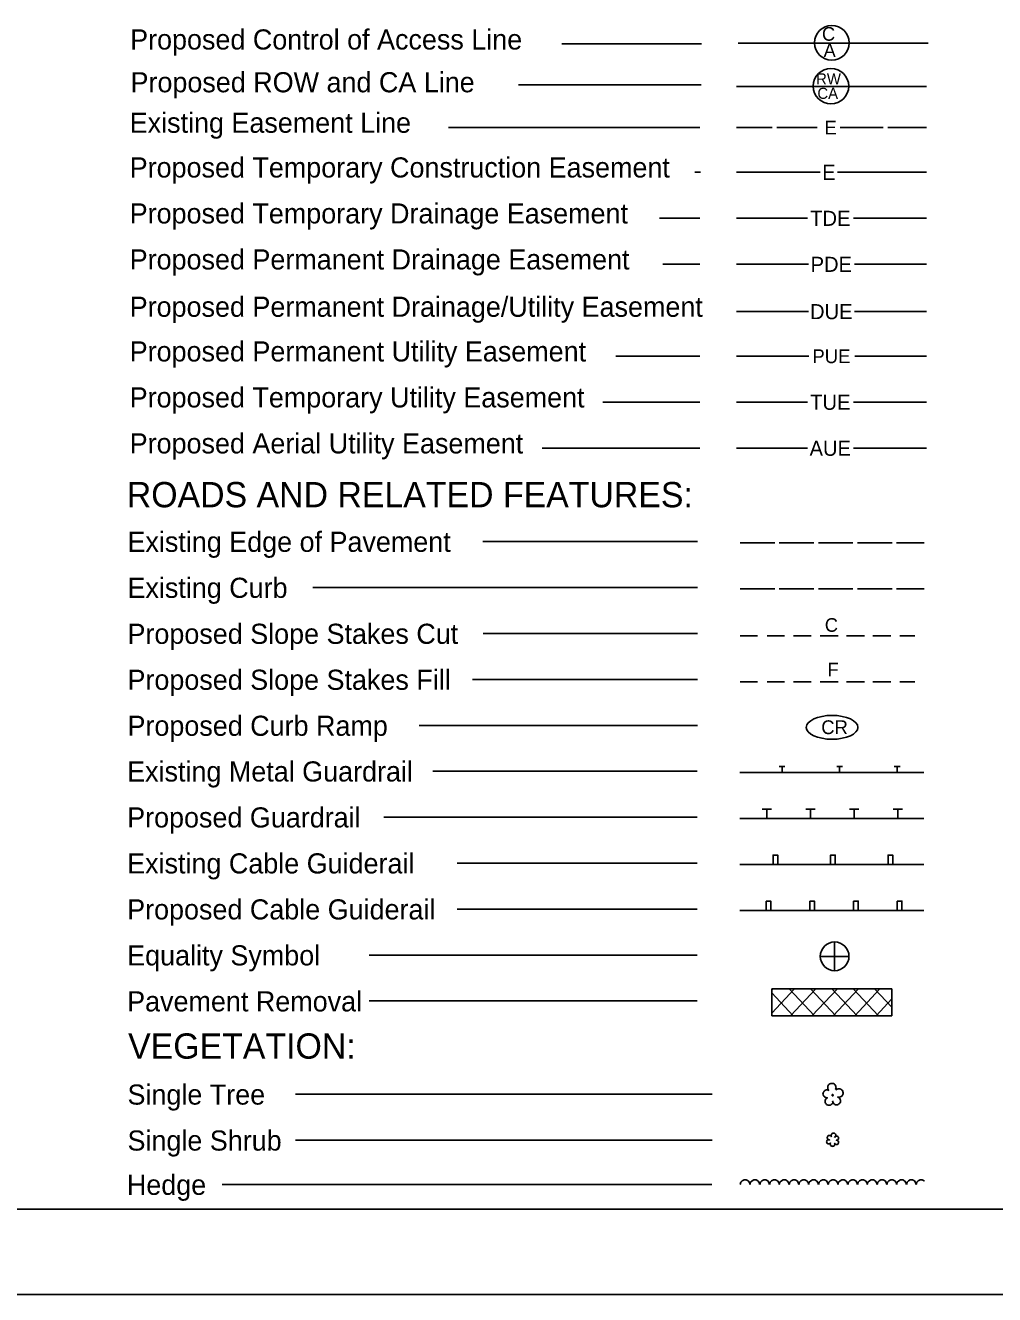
# Model space of a CAD drawing. Extents: x 1552903 to 1553044, y 811448 to 811540.
# Drawn here: x 1552937.98 to 1552973.4, y 811448.42 to 811494.83 of the extents above; entities that cross this region are included whole.
import ezdxf

# ---------------------------------------------------------------- set-up
doc = ezdxf.new("R2010")
doc.units = 0
for name, color, linetype in [('Exist DTM Breakline', 7, 'Continuous'), ('Exist Structure Major Bridge WW', 7, 'Continuous'), ('P_RDY_Easement_Permanent_Drainage_Utility', 7, 'Continuous'), ('P_RDY_WCC_CELL', 7, 'Continuous'), ('z - Construction', 7, 'Continuous')]:
    doc.layers.add(name, color=color, linetype=linetype)

msp = doc.modelspace()

# ---------------------------------------------------------------- linework, layer by layer
at = {"layer": 'Exist DTM Breakline'}
for p, q in [((1552962.683, 811494.155), (1552957.579, 811494.155)), ((1552964.031, 811494.186), (1552970.967, 811494.186)), ((1552962.675, 811492.662), (1552956.002, 811492.662)), ((1552963.97, 811492.597), (1552970.906, 811492.597)), ((1552962.621, 811491.096), (1552953.436, 811491.096)), ((1552963.969, 811491.096), (1552965.273, 811491.096)), ((1552965.441, 811491.096), (1552966.913, 811491.096)), ((1552967.754, 811491.096), (1552969.33, 811491.096)), ((1552969.498, 811491.096), (1552970.905, 811491.096)), ((1552962.654, 811489.461), (1552962.442, 811489.461)), ((1552963.969, 811489.461), (1552964.189, 811489.461)), ((1552964.189, 811489.461), (1552967.026, 811489.461)), ((1552967.657, 811489.461), (1552970.495, 811489.461)), ((1552970.495, 811489.461), (1552970.905, 811489.461)), ((1552962.621, 811487.779), (1552961.15, 811487.779)), ((1552963.969, 811487.779), (1552964.251, 811487.779)), ((1552964.251, 811487.779), (1552966.563, 811487.779)), ((1552968.244, 811487.779), (1552970.557, 811487.779)), ((1552970.557, 811487.779), (1552970.905, 811487.779)), ((1552962.621, 811486.098), (1552961.275, 811486.098)), ((1552963.969, 811486.098), (1552964.289, 811486.098)), ((1552964.289, 811486.098), (1552966.601, 811486.098)), ((1552968.282, 811486.098), (1552970.594, 811486.098)), ((1552970.594, 811486.098), (1552970.905, 811486.098)), ((1552962.621, 811482.734), (1552959.56, 811482.734)), ((1552963.969, 811482.734), (1552964.292, 811482.734)), ((1552964.292, 811482.734), (1552966.604, 811482.734)), ((1552968.285, 811482.734), (1552970.598, 811482.734)), ((1552970.598, 811482.734), (1552970.905, 811482.734)), ((1552962.621, 811481.052), (1552959.078, 811481.052)), ((1552963.969, 811481.052), (1552964.251, 811481.052)), ((1552964.251, 811481.052), (1552966.563, 811481.052)), ((1552968.244, 811481.052), (1552970.557, 811481.052)), ((1552970.557, 811481.052), (1552970.905, 811481.052)), ((1552962.621, 811479.371), (1552956.866, 811479.371)), ((1552963.969, 811479.371), (1552964.251, 811479.371)), ((1552964.251, 811479.371), (1552966.563, 811479.371)), ((1552968.244, 811479.371), (1552970.557, 811479.371)), ((1552970.557, 811479.371), (1552970.905, 811479.371)), ((1552962.54, 811475.963), (1552954.701, 811475.963)), ((1552964.098, 811475.915), (1552965.36, 811475.915)), ((1552965.528, 811475.915), (1552966.789, 811475.915)), ((1552966.957, 811475.915), (1552968.218, 811475.915)), ((1552968.386, 811475.915), (1552969.648, 811475.915)), ((1552969.816, 811475.915), (1552970.825, 811475.915)), ((1552962.54, 811474.282), (1552948.487, 811474.282)), ((1552964.098, 811474.233), (1552965.36, 811474.233)), ((1552965.528, 811474.233), (1552966.789, 811474.233)), ((1552966.957, 811474.233), (1552968.218, 811474.233)), ((1552968.386, 811474.233), (1552969.648, 811474.233)), ((1552969.816, 811474.233), (1552970.825, 811474.233)), ((1552962.54, 811472.6), (1552954.705, 811472.6)), ((1552964.098, 811472.512), (1552964.737, 811472.512)), ((1552965.721, 811472.512), (1552965.086, 811472.512)), ((1552966.688, 811472.512), (1552966.049, 811472.512)), ((1552967.676, 811472.512), (1552967.02, 811472.512)), ((1552968.639, 811472.512), (1552967.987, 811472.512)), ((1552969.61, 811472.512), (1552968.95, 811472.512)), ((1552970.476, 811472.512), (1552969.938, 811472.512)), ((1552962.54, 811470.918), (1552954.323, 811470.918)), ((1552964.098, 811470.83), (1552964.737, 811470.83)), ((1552965.721, 811470.83), (1552965.086, 811470.83)), ((1552966.688, 811470.83), (1552966.049, 811470.83)), ((1552967.676, 811470.83), (1552967.02, 811470.83)), ((1552968.639, 811470.83), (1552967.987, 811470.83)), ((1552969.61, 811470.83), (1552968.95, 811470.83)), ((1552970.476, 811470.83), (1552969.938, 811470.83)), ((1552962.54, 811469.237), (1552952.373, 811469.237)), ((1552962.527, 811467.565), (1552952.872, 811467.565)), ((1552964.085, 811467.517), (1552970.811, 811467.517)), ((1552965.526, 811467.727), (1552965.736, 811467.727)), ((1552965.631, 811467.517), (1552965.631, 811467.727)), ((1552967.628, 811467.727), (1552967.838, 811467.727)), ((1552967.733, 811467.517), (1552967.733, 811467.727)), ((1552969.73, 811467.727), (1552969.94, 811467.727)), ((1552969.835, 811467.517), (1552969.835, 811467.727)), ((1552964.903, 811466.168), (1552965.239, 811466.168)), ((1552965.071, 811465.835), (1552965.071, 811466.168)), ((1552966.5, 811466.168), (1552966.837, 811466.168)), ((1552966.669, 811465.835), (1552966.669, 811466.168)), ((1552968.098, 811466.168), (1552968.434, 811466.168)), ((1552968.266, 811465.835), (1552968.266, 811466.168)), ((1552969.695, 811466.168), (1552970.032, 811466.168)), ((1552969.863, 811465.835), (1552969.863, 811466.168)), ((1552962.527, 811465.884), (1552951.073, 811465.884)), ((1552970.811, 811465.835), (1552964.085, 811465.835)), ((1552962.527, 811464.202), (1552953.758, 811464.202)), ((1552964.085, 811464.154), (1552970.811, 811464.154)), ((1552962.527, 811462.521), (1552953.758, 811462.521)), ((1552964.085, 811462.472), (1552970.811, 811462.472)), ((1552967.551, 811461.315), (1552967.551, 811460.79)), ((1552962.527, 811460.839), (1552950.536, 811460.839)), ((1552967.026, 811460.79), (1552967.551, 811460.79)), ((1552967.551, 811460.79), (1552967.551, 811460.264)), ((1552967.551, 811460.79), (1552968.077, 811460.79)), ((1552965.258, 811459.602), (1552969.639, 811459.602)), ((1552965.258, 811458.618), (1552965.258, 811459.602)), ((1552965.258, 811459.552), (1552965.304, 811459.602)), ((1552965.258, 811458.715), (1552966.086, 811459.602)), ((1552966.818, 811458.618), (1552965.893, 811459.602)), ((1552965.943, 811458.618), (1552966.868, 811459.602)), ((1552967.595, 811458.618), (1552966.675, 811459.602)), ((1552966.721, 811458.618), (1552967.65, 811459.602)), ((1552968.377, 811458.618), (1552967.453, 811459.602)), ((1552967.503, 811458.618), (1552968.428, 811459.602)), ((1552969.159, 811458.618), (1552968.23, 811459.602)), ((1552968.285, 811458.618), (1552969.206, 811459.602)), ((1552969.639, 811458.934), (1552969.012, 811459.602)), ((1552969.639, 811459.602), (1552969.639, 811458.618)), ((1552962.527, 811459.158), (1552950.536, 811459.158)), ((1552966.036, 811458.618), (1552965.258, 811459.451)), ((1552969.063, 811458.618), (1552969.639, 811459.232)), ((1552969.639, 811458.618), (1552965.258, 811458.618)), ((1552963.081, 811455.749), (1552947.852, 811455.749)), ((1552963.081, 811454.067), (1552947.852, 811454.067)), ((1552963.058, 811452.448), (1552945.176, 811452.448)), ((1552964.1, 811452.448), (1552964.125, 811452.528)), ((1552964.125, 811452.528), (1552964.176, 811452.582)), ((1552964.176, 811452.582), (1552964.243, 811452.62)), ((1552964.243, 811452.62), (1552964.323, 811452.62)), ((1552964.323, 811452.62), (1552964.39, 811452.578)), ((1552964.39, 811452.578), (1552964.436, 811452.524)), ((1552964.436, 811452.524), (1552964.453, 811452.452)), ((1552964.457, 811452.448), (1552964.482, 811452.528)), ((1552964.482, 811452.528), (1552964.533, 811452.582)), ((1552964.533, 811452.582), (1552964.6, 811452.62)), ((1552964.6, 811452.62), (1552964.68, 811452.62)), ((1552964.68, 811452.62), (1552964.747, 811452.578)), ((1552964.747, 811452.578), (1552964.794, 811452.524)), ((1552964.794, 811452.524), (1552964.81, 811452.452)), ((1552964.815, 811452.448), (1552964.84, 811452.528)), ((1552964.84, 811452.528), (1552964.89, 811452.582)), ((1552964.89, 811452.582), (1552964.958, 811452.62)), ((1552964.958, 811452.62), (1552965.037, 811452.62)), ((1552965.037, 811452.62), (1552965.105, 811452.578)), ((1552965.105, 811452.578), (1552965.151, 811452.524)), ((1552965.151, 811452.524), (1552965.168, 811452.452)), ((1552965.172, 811452.448), (1552965.197, 811452.528)), ((1552965.197, 811452.528), (1552965.248, 811452.582)), ((1552965.248, 811452.582), (1552965.315, 811452.62)), ((1552965.315, 811452.62), (1552965.395, 811452.62)), ((1552965.395, 811452.62), (1552965.462, 811452.578)), ((1552965.462, 811452.578), (1552965.508, 811452.524)), ((1552965.508, 811452.524), (1552965.525, 811452.452)), ((1552965.529, 811452.448), (1552965.554, 811452.528)), ((1552965.554, 811452.528), (1552965.605, 811452.582)), ((1552965.605, 811452.582), (1552965.672, 811452.62)), ((1552965.672, 811452.62), (1552965.752, 811452.62)), ((1552965.752, 811452.62), (1552965.819, 811452.578)), ((1552965.819, 811452.578), (1552965.866, 811452.524)), ((1552965.866, 811452.524), (1552965.882, 811452.452)), ((1552965.887, 811452.448), (1552965.912, 811452.528)), ((1552965.912, 811452.528), (1552965.962, 811452.582)), ((1552965.962, 811452.582), (1552966.03, 811452.62)), ((1552966.03, 811452.62), (1552966.109, 811452.62)), ((1552966.109, 811452.62), (1552966.177, 811452.578)), ((1552966.177, 811452.578), (1552966.223, 811452.524)), ((1552966.223, 811452.524), (1552966.24, 811452.452)), ((1552966.244, 811452.448), (1552966.269, 811452.528)), ((1552966.269, 811452.528), (1552966.32, 811452.582)), ((1552966.32, 811452.582), (1552966.387, 811452.62)), ((1552966.387, 811452.62), (1552966.467, 811452.62)), ((1552966.467, 811452.62), (1552966.534, 811452.578)), ((1552966.534, 811452.578), (1552966.58, 811452.524)), ((1552966.58, 811452.524), (1552966.597, 811452.452)), ((1552966.601, 811452.448), (1552966.626, 811452.528)), ((1552966.626, 811452.528), (1552966.677, 811452.582)), ((1552966.677, 811452.582), (1552966.744, 811452.62)), ((1552966.744, 811452.62), (1552966.824, 811452.62)), ((1552966.824, 811452.62), (1552966.891, 811452.578)), ((1552966.891, 811452.578), (1552966.938, 811452.524)), ((1552966.938, 811452.524), (1552966.954, 811452.452)), ((1552966.959, 811452.448), (1552966.984, 811452.528)), ((1552966.984, 811452.528), (1552967.034, 811452.582)), ((1552967.034, 811452.582), (1552967.102, 811452.62)), ((1552967.102, 811452.62), (1552967.181, 811452.62)), ((1552967.181, 811452.62), (1552967.249, 811452.578)), ((1552967.249, 811452.578), (1552967.295, 811452.524)), ((1552967.295, 811452.524), (1552967.312, 811452.452)), ((1552967.316, 811452.448), (1552967.341, 811452.528)), ((1552967.341, 811452.528), (1552967.392, 811452.582)), ((1552967.392, 811452.582), (1552967.459, 811452.62)), ((1552967.459, 811452.62), (1552967.539, 811452.62)), ((1552967.539, 811452.62), (1552967.606, 811452.578)), ((1552967.606, 811452.578), (1552967.652, 811452.524)), ((1552967.652, 811452.524), (1552967.669, 811452.452)), ((1552967.673, 811452.448), (1552967.698, 811452.528)), ((1552967.698, 811452.528), (1552967.749, 811452.582)), ((1552967.749, 811452.582), (1552967.816, 811452.62)), ((1552967.816, 811452.62), (1552967.896, 811452.62)), ((1552967.896, 811452.62), (1552967.963, 811452.578)), ((1552967.963, 811452.578), (1552968.01, 811452.524)), ((1552968.01, 811452.524), (1552968.026, 811452.452)), ((1552968.031, 811452.448), (1552968.056, 811452.528)), ((1552968.056, 811452.528), (1552968.106, 811452.582)), ((1552968.106, 811452.582), (1552968.174, 811452.62)), ((1552968.174, 811452.62), (1552968.253, 811452.62)), ((1552968.253, 811452.62), (1552968.321, 811452.578)), ((1552968.321, 811452.578), (1552968.367, 811452.524)), ((1552968.367, 811452.524), (1552968.384, 811452.452)), ((1552968.388, 811452.448), (1552968.413, 811452.528)), ((1552968.413, 811452.528), (1552968.464, 811452.582)), ((1552968.464, 811452.582), (1552968.531, 811452.62)), ((1552968.531, 811452.62), (1552968.611, 811452.62)), ((1552968.611, 811452.62), (1552968.678, 811452.578)), ((1552968.678, 811452.578), (1552968.724, 811452.524)), ((1552968.724, 811452.524), (1552968.741, 811452.452)), ((1552968.745, 811452.448), (1552968.77, 811452.528)), ((1552968.77, 811452.528), (1552968.821, 811452.582)), ((1552968.821, 811452.582), (1552968.888, 811452.62)), ((1552968.888, 811452.62), (1552968.968, 811452.62)), ((1552968.968, 811452.62), (1552969.035, 811452.578)), ((1552969.035, 811452.578), (1552969.082, 811452.524)), ((1552969.082, 811452.524), (1552969.098, 811452.452)), ((1552969.103, 811452.448), (1552969.128, 811452.528)), ((1552969.128, 811452.528), (1552969.178, 811452.582)), ((1552969.178, 811452.582), (1552969.245, 811452.62)), ((1552969.245, 811452.62), (1552969.325, 811452.62)), ((1552969.325, 811452.62), (1552969.393, 811452.578)), ((1552969.393, 811452.578), (1552969.439, 811452.524)), ((1552969.439, 811452.524), (1552969.456, 811452.452)), ((1552969.46, 811452.448), (1552969.485, 811452.528)), ((1552969.485, 811452.528), (1552969.536, 811452.582)), ((1552969.536, 811452.582), (1552969.603, 811452.62)), ((1552969.603, 811452.62), (1552969.683, 811452.62)), ((1552969.683, 811452.62), (1552969.75, 811452.578)), ((1552969.75, 811452.578), (1552969.796, 811452.524)), ((1552969.796, 811452.524), (1552969.813, 811452.452)), ((1552969.817, 811452.448), (1552969.842, 811452.528)), ((1552969.842, 811452.528), (1552969.893, 811452.582)), ((1552969.893, 811452.582), (1552969.96, 811452.62)), ((1552969.96, 811452.62), (1552970.04, 811452.62)), ((1552970.04, 811452.62), (1552970.107, 811452.578)), ((1552970.107, 811452.578), (1552970.154, 811452.524)), ((1552970.154, 811452.524), (1552970.17, 811452.452)), ((1552970.175, 811452.448), (1552970.2, 811452.528)), ((1552970.2, 811452.528), (1552970.25, 811452.582)), ((1552970.25, 811452.582), (1552970.317, 811452.62)), ((1552970.317, 811452.62), (1552970.397, 811452.62)), ((1552970.397, 811452.62), (1552970.465, 811452.578)), ((1552970.465, 811452.578), (1552970.511, 811452.524)), ((1552970.511, 811452.524), (1552970.528, 811452.452)), ((1552970.532, 811452.448), (1552970.557, 811452.528)), ((1552970.557, 811452.528), (1552970.608, 811452.582)), ((1552970.608, 811452.582), (1552970.675, 811452.62)), ((1552970.675, 811452.62), (1552970.755, 811452.62)), ((1552970.755, 811452.62), (1552970.822, 811452.578)), ((1552970.822, 811452.578), (1552970.826, 811452.574))]:
    msp.add_line(p, q, dxfattribs=at)
for points in [[(1552965.302, 811464.154), (1552965.47, 811464.154), (1552965.47, 811464.49), (1552965.302, 811464.49)], [(1552967.404, 811464.154), (1552967.572, 811464.154), (1552967.572, 811464.49), (1552967.404, 811464.49)], [(1552969.506, 811464.154), (1552969.674, 811464.154), (1552969.674, 811464.49), (1552969.506, 811464.49)], [(1552965.049, 811462.809), (1552965.217, 811462.809), (1552965.217, 811462.472), (1552965.049, 811462.472)], [(1552966.646, 811462.809), (1552966.815, 811462.809), (1552966.815, 811462.472), (1552966.646, 811462.472)], [(1552968.244, 811462.809), (1552968.412, 811462.809), (1552968.412, 811462.472), (1552968.244, 811462.472)], [(1552969.841, 811462.809), (1552970.01, 811462.809), (1552970.01, 811462.472), (1552969.841, 811462.472)]]:
    msp.add_lwpolyline(points, close=True, dxfattribs=at)
for points in [[(1552967.582, 811455.924), (1552967.595, 811455.954), (1552967.601, 811455.984), (1552967.598, 811456.017), (1552967.591, 811456.047), (1552967.575, 811456.076), (1552967.558, 811456.1), (1552967.532, 811456.123), (1552967.505, 811456.136), (1552967.472, 811456.146), (1552967.443, 811456.146), (1552967.409, 811456.143), (1552967.38, 811456.133), (1552967.353, 811456.116), (1552967.33, 811456.093), (1552967.313, 811456.067), (1552967.3, 811456.037), (1552967.297, 811456.007), (1552967.297, 811455.974), (1552967.303, 811455.944), (1552967.317, 811455.914), (1552967.337, 811455.888), (1552967.31, 811455.901), (1552967.28, 811455.908), (1552967.251, 811455.904), (1552967.221, 811455.898), (1552967.194, 811455.884), (1552967.168, 811455.865), (1552967.151, 811455.841), (1552967.135, 811455.815), (1552967.128, 811455.788), (1552967.125, 811455.755), (1552967.128, 811455.726), (1552967.141, 811455.699), (1552967.158, 811455.673), (1552967.178, 811455.653), (1552967.204, 811455.636), (1552967.231, 811455.623), (1552967.26, 811455.62), (1552967.29, 811455.62), (1552967.264, 811455.606), (1552967.241, 811455.587), (1552967.224, 811455.563), (1552967.211, 811455.534), (1552967.204, 811455.504), (1552967.201, 811455.474), (1552967.208, 811455.444), (1552967.221, 811455.418), (1552967.237, 811455.391), (1552967.257, 811455.371), (1552967.284, 811455.355), (1552967.313, 811455.345), (1552967.343, 811455.342), (1552967.373, 811455.345), (1552967.403, 811455.352), (1552967.429, 811455.368), (1552967.452, 811455.388), (1552967.469, 811455.411), (1552967.482, 811455.438), (1552967.489, 811455.467)], [(1552967.479, 811455.504), (1552967.482, 811455.471), (1552967.492, 811455.441), (1552967.509, 811455.414), (1552967.532, 811455.391), (1552967.558, 811455.375), (1552967.588, 811455.365), (1552967.621, 811455.361), (1552967.651, 811455.365), (1552967.681, 811455.375), (1552967.707, 811455.391), (1552967.73, 811455.411), (1552967.75, 811455.438), (1552967.76, 811455.467), (1552967.767, 811455.497), (1552967.764, 811455.53), (1552967.757, 811455.56), (1552967.74, 811455.59), (1552967.721, 811455.613), (1552967.694, 811455.63), (1552967.664, 811455.643), (1552967.697, 811455.64), (1552967.73, 811455.64), (1552967.76, 811455.649), (1552967.79, 811455.663), (1552967.817, 811455.683), (1552967.836, 811455.709), (1552967.853, 811455.739), (1552967.86, 811455.769), (1552967.863, 811455.802), (1552967.856, 811455.835), (1552967.846, 811455.865), (1552967.827, 811455.891), (1552967.803, 811455.914), (1552967.777, 811455.931), (1552967.744, 811455.944), (1552967.714, 811455.947), (1552967.681, 811455.947), (1552967.648, 811455.937), (1552967.621, 811455.921), (1552967.595, 811455.901)], [(1552967.489, 811455.739), (1552967.476, 811455.739), (1552967.462, 811455.735), (1552967.456, 811455.726), (1552967.452, 811455.712), (1552967.456, 811455.699), (1552967.466, 811455.689), (1552967.479, 811455.689), (1552967.492, 811455.692), (1552967.502, 811455.702), (1552967.505, 811455.716), (1552967.499, 811455.729), (1552967.489, 811455.739)], [(1552967.439, 811454.19), (1552967.429, 811454.21), (1552967.409, 811454.226), (1552967.39, 811454.239), (1552967.366, 811454.243), (1552967.343, 811454.239), (1552967.32, 811454.233), (1552967.3, 811454.216), (1552967.287, 811454.196), (1552967.28, 811454.173), (1552967.28, 811454.15), (1552967.287, 811454.127), (1552967.3, 811454.107), (1552967.32, 811454.09), (1552967.343, 811454.08), (1552967.366, 811454.08), (1552967.343, 811454.084), (1552967.32, 811454.084), (1552967.3, 811454.077), (1552967.28, 811454.064), (1552967.267, 811454.047), (1552967.26, 811454.027), (1552967.257, 811454.004), (1552967.26, 811453.981), (1552967.27, 811453.961), (1552967.287, 811453.945), (1552967.307, 811453.935), (1552967.327, 811453.928), (1552967.35, 811453.931), (1552967.37, 811453.938), (1552967.39, 811453.951), (1552967.403, 811453.968), (1552967.393, 811453.945), (1552967.39, 811453.922), (1552967.396, 811453.898), (1552967.406, 811453.879), (1552967.423, 811453.859), (1552967.443, 811453.849), (1552967.466, 811453.842), (1552967.489, 811453.845), (1552967.512, 811453.852), (1552967.532, 811453.865), (1552967.545, 811453.885), (1552967.555, 811453.908), (1552967.555, 811453.931), (1552967.552, 811453.955), (1552967.562, 811453.938), (1552967.582, 811453.922), (1552967.601, 811453.915), (1552967.625, 811453.912), (1552967.648, 811453.915), (1552967.668, 811453.925), (1552967.684, 811453.941), (1552967.694, 811453.961), (1552967.697, 811453.984), (1552967.697, 811454.008), (1552967.688, 811454.027), (1552967.674, 811454.044), (1552967.658, 811454.057), (1552967.635, 811454.067), (1552967.611, 811454.067), (1552967.635, 811454.067), (1552967.658, 811454.074), (1552967.674, 811454.087), (1552967.691, 811454.107), (1552967.697, 811454.127), (1552967.697, 811454.15), (1552967.694, 811454.173), (1552967.681, 811454.193), (1552967.664, 811454.206), (1552967.641, 811454.216), (1552967.618, 811454.219), (1552967.598, 811454.213), (1552967.575, 811454.203), (1552967.562, 811454.186), (1552967.552, 811454.166)], [(1552967.542, 811454.166), (1552967.562, 811454.176), (1552967.578, 811454.196), (1552967.588, 811454.216), (1552967.591, 811454.239), (1552967.591, 811454.262), (1552967.582, 811454.286), (1552967.568, 811454.302), (1552967.552, 811454.319), (1552967.529, 811454.325), (1552967.505, 811454.329), (1552967.482, 811454.325), (1552967.462, 811454.315), (1552967.443, 811454.299), (1552967.433, 811454.279), (1552967.426, 811454.256), (1552967.426, 811454.233), (1552967.429, 811454.21), (1552967.443, 811454.19)]]:
    msp.add_lwpolyline(points, dxfattribs=at)
for centre, radius in [((1552967.448, 811494.195), 0.637), ((1552967.416, 811492.609), 0.649)]:
    msp.add_circle(centre, radius, dxfattribs=at)
for start, end in [(89.9944, 179.9989), (359.9944, 89.9989), (179.9944, 269.9989), (269.9944, 359.9989)]:
    msp.add_arc((1552967.551, 811460.79), 0.525, start, end, dxfattribs=at)
at = {"layer": 'Exist Structure Major Bridge WW'}
msp.add_line((1552905.688, 811451.545), (1553041.103, 811451.545), dxfattribs=at)
at = {"layer": 'P_RDY_Easement_Permanent_Drainage_Utility'}
for p, q in [((1552963.969, 811484.367), (1552966.601, 811484.367)), ((1552968.282, 811484.367), (1552970.905, 811484.367))]:
    msp.add_line(p, q, dxfattribs=at)
at = {"layer": 'P_RDY_WCC_CELL'}
msp.add_ellipse((1552967.458, 811469.164), major_axis=(0.943, 0), ratio=0.462467, dxfattribs=at)
at = {"layer": 'z - Construction'}
msp.add_line((1552902.563, 811448.42), (1553044.23, 811448.42), dxfattribs=at)

# ---------------------------------------------------------------- texts
at = {"layer": 'Exist DTM Breakline'}
for s, height, p in [('Proposed Control of Access Line', 0.73569, (1552941.807, 811493.95)), ('C', 0.499, (1552967.088, 811494.271)), ('A', 0.499, (1552967.147, 811493.671)), ('Proposed ROW and CA Line', 0.73569, (1552941.821, 811492.386)), ('RW', 0.4068, (1552966.874, 811492.674)), ('CA', 0.4068, (1552966.921, 811492.145)), ('Existing Easement Line', 0.73569, (1552941.791, 811490.906)), ('E', 0.504, (1552967.182, 811490.844)), ('Proposed Temporary Construction Easement', 0.73569, (1552941.791, 811489.27)), ('E', 0.551, (1552967.098, 811489.183)), ('Proposed Temporary Drainage Easement', 0.73569, (1552941.791, 811487.589)), ('TDE', 0.5507, (1552966.656, 811487.502)), ('Proposed Permanent Drainage Easement', 0.73569, (1552941.791, 811485.907)), ('PDE', 0.5507, (1552966.672, 811485.82)), ('Proposed Permanent Drainage/Utility Easement', 0.73569, (1552941.791, 811484.177)), ('Proposed Permanent Utility Easement', 0.73569, (1552941.791, 811482.543)), ('PUE', 0.5045, (1552966.739, 811482.481)), ('Proposed Temporary Utility Easement', 0.73569, (1552941.791, 811480.862)), ('TUE', 0.5507, (1552966.656, 811480.775)), ('Proposed Aerial Utility Easement', 0.73569, (1552941.791, 811479.18)), ('AUE', 0.5507, (1552966.635, 811479.093)), ('ROADS AND RELATED FEATURES:', 0.92486, (1552941.685, 811477.211)), ('Existing Edge of Pavement', 0.73569, (1552941.71, 811475.581)), ('Existing Curb', 0.73569, (1552941.71, 811473.899)), ('C', 0.498, (1552967.192, 811472.658)), ('Proposed Slope Stakes Cut', 0.73569, (1552941.71, 811472.217)), ('Proposed Slope Stakes Fill', 0.73569, (1552941.71, 811470.536)), ('F', 0.498, (1552967.293, 811471.029)), ('Proposed Curb Ramp', 0.73569, (1552941.71, 811468.854)), ('Existing Metal Guardrail', 0.73569, (1552941.697, 811467.183)), ('Proposed Guardrail', 0.73569, (1552941.698, 811465.502)), ('Existing Cable Guiderail', 0.73569, (1552941.698, 811463.821)), ('Proposed Cable Guiderail', 0.73569, (1552941.698, 811462.139)), ('Equality Symbol', 0.73569, (1552941.698, 811460.458)), ('Pavement Removal', 0.73569, (1552941.698, 811458.776)), ('VEGETATION:', 0.92486, (1552941.734, 811457.048)), ('Single Tree', 0.73569, (1552941.711, 811455.368)), ('Single Shrub', 0.73569, (1552941.711, 811453.687)), ('Hedge', 0.7357, (1552941.688, 811452.068))]:
    msp.add_text(s, height=height, dxfattribs=at).set_placement(p)
at = {"layer": 'P_RDY_Easement_Permanent_Drainage_Utility'}
msp.add_text('DUE', height=0.5507, dxfattribs=at).set_placement((1552966.651, 811484.09))
at = {"layer": 'P_RDY_WCC_CELL'}
msp.add_text('CR', height=0.5045, dxfattribs=at).set_placement((1552967.062, 811468.916))

doc.saveas('drawing.dxf')
